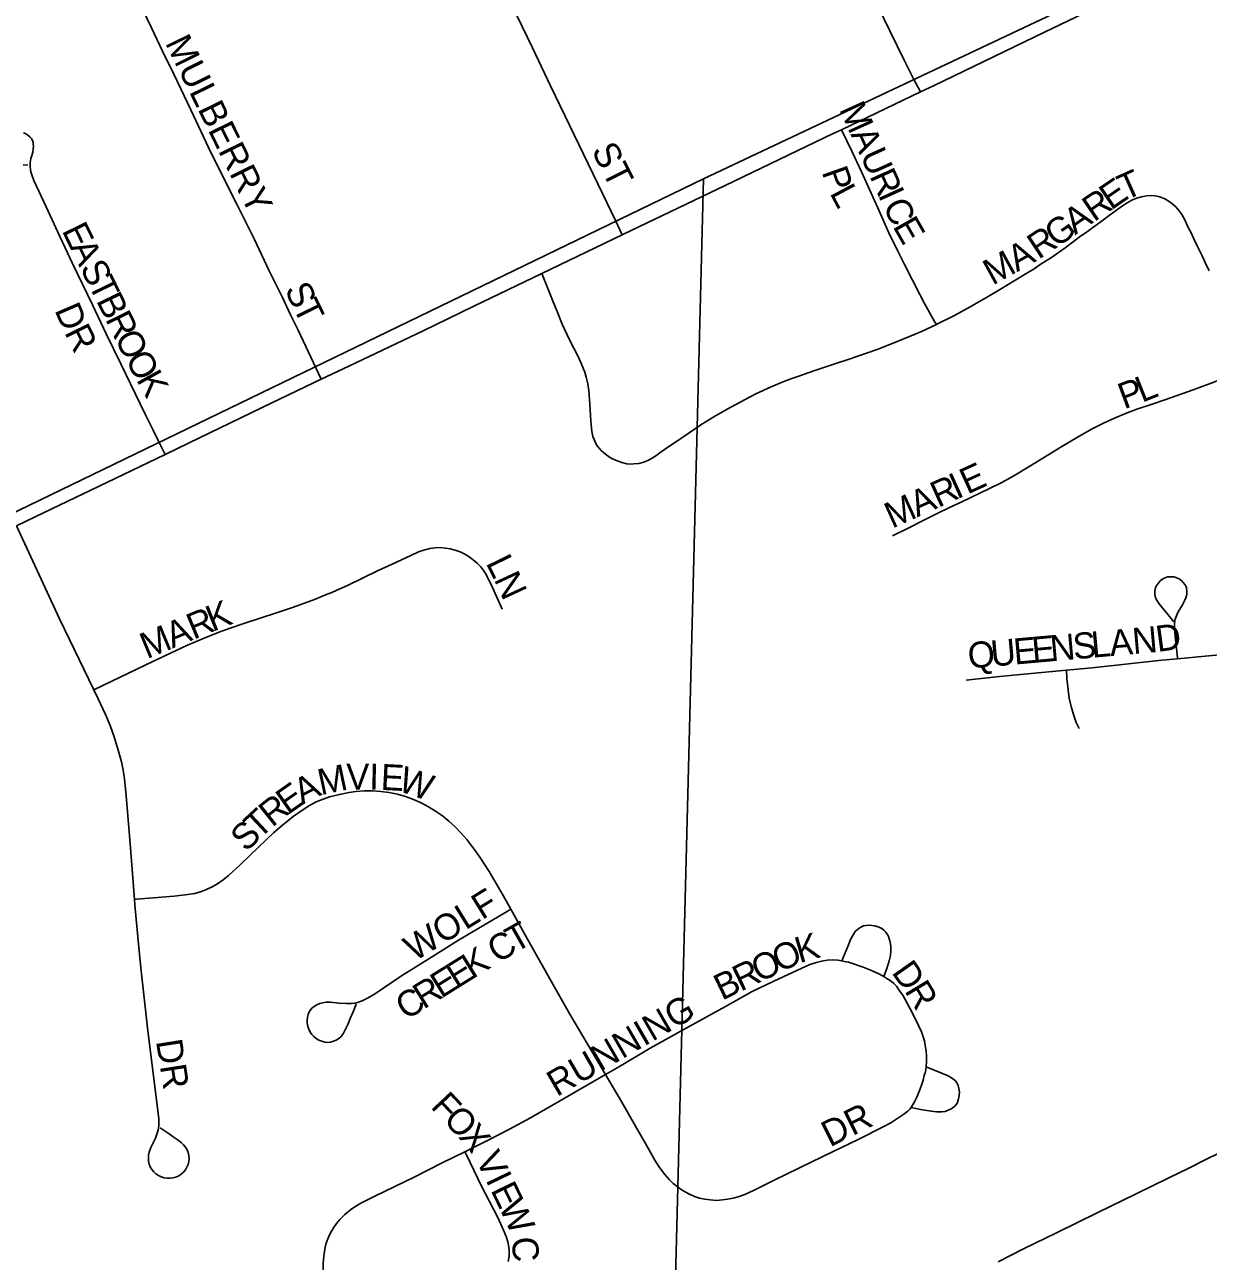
# Model space of a CAD drawing. Extents: x -5.6 to 34, y 0 to 22.
# Drawn here: x 4.822 to 5.73, y 19.139 to 20.089 of the extents above; entities that cross this region are included whole.
import ezdxf

# ---------------------------------------------------------------- set-up
doc = ezdxf.new("R2010")
doc.units = 0
for name, color, linetype in [('GM_X_City_Street', 7, 'Continuous'), ('GM_X_City_Street_Text', 7, 'Continuous'), ('GM_X_Section', 7, 'Continuous')]:
    doc.layers.add(name, color=color, linetype=linetype)

msp = doc.modelspace()

# ---------------------------------------------------------------- linework, layer by layer
at = {"layer": 'GM_X_City_Street'}
for points in [[(5.50953, 20.03721), (5.5046, 20.0469), (5.49712, 20.0616), (5.48598, 20.08416), (5.47718, 20.10263), (5.46985, 20.11815), (5.46339, 20.13133), (5.4585, 20.14256), (5.4546, 20.15067), (5.45137, 20.1574), (5.44667, 20.16679), (5.44052, 20.17967), (5.43679, 20.18727), (5.42703, 20.20751), (5.41793, 20.22684), (5.39456, 20.2753), (5.39379, 20.27694)], [(5.28072, 19.92757), (5.27549, 19.93857), (5.26565, 19.95932), (5.22564, 20.042), (5.21184, 20.071), (5.2001, 20.0953), (5.18545, 20.12579), (5.17342, 20.15127), (5.16593, 20.16686)], [(5.50953, 20.03721), (5.5196, 20.04202), (5.60472, 20.08318), (5.67096, 20.11508), (5.69762, 20.12785)], [(5.04967, 19.81662), (5.04581, 19.82478), (5.0316, 19.85482), (5.02615, 19.86609), (5.01999, 19.87927), (5.00943, 19.90037), (4.99841, 19.92381), (4.9848, 19.95105), (4.96515, 19.9903), (4.9496, 20.02341), (4.9367, 20.05037), (4.92789, 20.06853), (4.91931, 20.08641), (4.90619, 20.11424)], [(5.44896, 20.00822), (5.50953, 20.03721)], [(5.28072, 19.92757), (5.28158, 19.92799), (5.3597, 19.9655), (5.44262, 20.00519), (5.44896, 20.00822)], [(5.52176, 19.8586), (5.52043, 19.86099), (5.51259, 19.87488), (5.50911, 19.88166), (5.50351, 19.89268), (5.49729, 19.90467), (5.49208, 19.915), (5.4854, 19.92911), (5.4768, 19.94836), (5.46443, 19.97593), (5.45716, 19.99112), (5.44896, 20.00822)], [(4.92978, 19.75883), (4.9243, 19.77016), (4.92044, 19.77813), (4.91459, 19.78983), (4.90338, 19.81297), (4.89574, 19.82849), (4.88467, 19.85151), (4.87415, 19.87386), (4.85852, 19.90606), (4.84757, 19.92957), (4.83854, 19.9489), (4.82894, 19.96927), (4.82742, 19.97345), (4.82656, 19.97681), (4.82623, 19.98036), (4.82624, 19.98293), (4.82687, 19.98612), (4.82755, 19.98843), (4.82822, 19.99108), (4.82866, 19.99351), (4.82873, 19.99541), (4.82866, 19.99727), (4.82843, 19.9987), (4.82778, 20.00037), (4.82721, 20.00137), (4.82601, 20.0028), (4.82446, 20.00412), (4.82301, 20.00512), (4.82114, 20.00578)], [(4.82093, 19.98091), (4.82447, 19.98124)], [(5.73117, 19.89987), (5.72813, 19.90625), (5.72569, 19.91129), (5.72197, 19.91898), (5.71943, 19.92431), (5.717, 19.92952), (5.71491, 19.93369), (5.71352, 19.93664), (5.71213, 19.93942), (5.71022, 19.94307), (5.70808, 19.94595), (5.70554, 19.94897), (5.70365, 19.95076), (5.70049, 19.95311), (5.69707, 19.95505), (5.69465, 19.95609), (5.69216, 19.9569), (5.68959, 19.95739), (5.68699, 19.9576), (5.68305, 19.95743), (5.67918, 19.95672), (5.67541, 19.95557), (5.6718, 19.954), (5.66835, 19.95211), (5.66397, 19.94923), (5.65999, 19.94637), (5.65545, 19.9431), (5.65028, 19.9394), (5.64159, 19.93297), (5.63691, 19.92966), (5.63149, 19.92559), (5.62579, 19.92131), (5.62075, 19.9175), (5.61641, 19.91436), (5.6093, 19.90949), (5.60234, 19.90515), (5.59679, 19.9015), (5.59123, 19.89802), (5.58287, 19.89289), (5.57108, 19.88567), (5.56031, 19.87941), (5.54553, 19.87088), (5.53515, 19.86525), (5.52224, 19.85882), (5.52176, 19.8586)], [(5.21888, 19.89774), (5.28072, 19.92757)], [(5.1467, 19.86297), (5.16686, 19.87265), (5.21888, 19.89774)], [(5.52176, 19.8586), (5.5103, 19.85339), (5.50548, 19.85131), (5.4873, 19.84377), (5.47625, 19.83958), (5.45396, 19.83181), (5.44527, 19.82886), (5.42785, 19.82311), (5.41553, 19.81882), (5.41072, 19.81719), (5.40469, 19.81495), (5.3951, 19.81082), (5.38322, 19.80532), (5.37506, 19.80112), (5.36128, 19.79352), (5.35098, 19.78772), (5.34091, 19.78154), (5.32783, 19.77276), (5.31377, 19.76309), (5.31061, 19.76079), (5.30753, 19.75849), (5.30426, 19.75633), (5.30081, 19.75449), (5.29717, 19.75306), (5.29338, 19.75204), (5.28948, 19.75154), (5.28686, 19.75151), (5.28425, 19.75176), (5.28041, 19.75256), (5.27671, 19.75387), (5.27314, 19.75553), (5.27089, 19.75687), (5.26774, 19.75921), (5.26485, 19.76167), (5.26304, 19.76358), (5.26144, 19.76559), (5.26011, 19.76788), (5.25905, 19.77028), (5.25821, 19.77277), (5.25736, 19.7766), (5.25671, 19.78183), (5.25652, 19.78444), (5.25581, 19.7975), (5.25491, 19.80797), (5.25418, 19.81315), (5.25304, 19.81828), (5.2519, 19.82204), (5.2495, 19.82813), (5.24678, 19.8341), (5.24023, 19.84697), (5.23469, 19.85887), (5.23064, 19.86856), (5.22707, 19.87742), (5.22346, 19.88639), (5.21888, 19.89774)], [(5.04967, 19.81662), (5.07091, 19.82676), (5.1278, 19.85389), (5.1467, 19.86297)], [(5.48813, 19.69629), (5.50077, 19.70248), (5.51314, 19.70883), (5.5225, 19.71348), (5.53194, 19.71802), (5.54141, 19.72255), (5.56267, 19.73268), (5.57201, 19.73743), (5.5812, 19.74248), (5.59358, 19.7499), (5.60808, 19.75886), (5.61816, 19.76502), (5.63054, 19.7724), (5.64082, 19.7782), (5.65016, 19.78297), (5.6585, 19.78679), (5.66694, 19.79037), (5.67553, 19.79357), (5.68673, 19.79715), (5.69789, 19.80095), (5.71893, 19.80836), (5.73486, 19.81441), (5.75184, 19.82152), (5.76526, 19.82774)], [(4.92978, 19.75883), (4.94787, 19.76754), (5.01167, 19.79847), (5.04967, 19.81662)], [(4.81572, 19.7041), (4.83069, 19.71128), (4.88515, 19.73739), (4.92978, 19.75883)], [(4.87507, 19.57818), (4.84867, 19.6326), (4.81572, 19.7041)], [(4.87507, 19.57818), (4.88904, 19.58483), (4.92099, 19.60006), (4.94705, 19.61242), (4.9615, 19.61864), (4.97246, 19.62301), (4.97985, 19.62546), (4.99027, 19.62894), (5.01599, 19.63756), (5.02846, 19.64163), (5.04444, 19.64752), (5.05415, 19.6515), (5.05661, 19.65242), (5.06974, 19.65836), (5.09334, 19.66981), (5.10413, 19.67458), (5.11831, 19.68139), (5.12432, 19.68402), (5.12927, 19.68575), (5.13309, 19.68667), (5.13699, 19.68719), (5.14091, 19.6873), (5.14484, 19.687), (5.14871, 19.68633), (5.15251, 19.68532), (5.15621, 19.68399), (5.15978, 19.68233), (5.16317, 19.68032), (5.16635, 19.67801), (5.16931, 19.67544), (5.17207, 19.67261), (5.17444, 19.6695), (5.17644, 19.66612), (5.18099, 19.65666), (5.18863, 19.63996)], [(5.70691, 19.60197), (5.70684, 19.60271), (5.70562, 19.61479), (5.70505, 19.61945), (5.70452, 19.62466), (5.70453, 19.6286), (5.70487, 19.6312), (5.70512, 19.63248), (5.70653, 19.63613), (5.70772, 19.63845), (5.71039, 19.64294), (5.71222, 19.64642), (5.71318, 19.64883), (5.71392, 19.65135), (5.71407, 19.65264), (5.7141, 19.65393), (5.71369, 19.65642), (5.71322, 19.6576), (5.71262, 19.65873), (5.71104, 19.66082), (5.71014, 19.66175), (5.70911, 19.66257), (5.70802, 19.6633), (5.70565, 19.66441), (5.7044, 19.66478), (5.70312, 19.66498), (5.70052, 19.66499), (5.69926, 19.66477), (5.69801, 19.6644), (5.69565, 19.66327), (5.69356, 19.66173), (5.69266, 19.66083), (5.69116, 19.65883), (5.69057, 19.65772), (5.69007, 19.65652), (5.68972, 19.65528), (5.68948, 19.65399), (5.68938, 19.65267), (5.68942, 19.65135), (5.68963, 19.65005), (5.68998, 19.6488), (5.69115, 19.64646), (5.69279, 19.64407), (5.69574, 19.64036), (5.69861, 19.63709), (5.70074, 19.63453), (5.70396, 19.63045)], [(5.70691, 19.60197), (5.72819, 19.60403), (5.74974, 19.60612), (5.78238, 19.60941), (5.81759, 19.6132), (5.83812, 19.6155)], [(5.62173, 19.59327), (5.64134, 19.59511), (5.69486, 19.6008), (5.70691, 19.60197)], [(5.54464, 19.58565), (5.57027, 19.58828), (5.58905, 19.59021), (5.62173, 19.59327)], [(5.63128, 19.54836), (5.62911, 19.55309), (5.62691, 19.5592), (5.62512, 19.56545), (5.62373, 19.5718), (5.62283, 19.57823), (5.62204, 19.58671), (5.62173, 19.59327)], [(4.90623, 19.41723), (4.90443, 19.44044), (4.90211, 19.46922), (4.90003, 19.49672), (4.89854, 19.50985), (4.89753, 19.51639), (4.89623, 19.52289), (4.89389, 19.53185), (4.89074, 19.54197), (4.88755, 19.55067), (4.88401, 19.55923), (4.87846, 19.5712), (4.87507, 19.57818)], [(4.90623, 19.41723), (4.90796, 19.41738), (4.93666, 19.41969), (4.94723, 19.42088), (4.95253, 19.42185), (4.95776, 19.42328), (4.96158, 19.42469), (4.96652, 19.427), (4.97005, 19.42906), (4.97448, 19.43218), (4.9786, 19.43563), (4.98732, 19.44372), (5.00156, 19.45743), (5.01305, 19.46828), (5.01993, 19.47431), (5.02804, 19.48083), (5.03543, 19.48601), (5.04068, 19.48943), (5.04577, 19.49223), (5.05124, 19.49429), (5.05607, 19.49591), (5.06359, 19.49788), (5.07116, 19.49941), (5.07624, 19.50009), (5.08264, 19.50049), (5.08908, 19.50044), (5.09551, 19.5), (5.10187, 19.49918), (5.10816, 19.49789), (5.11432, 19.49614), (5.12036, 19.49395), (5.12623, 19.49135), (5.13192, 19.48835), (5.13741, 19.48499), (5.14268, 19.4813), (5.1477, 19.47729), (5.15241, 19.47294), (5.15679, 19.46824), (5.16144, 19.46318), (5.16457, 19.45923), (5.16782, 19.45477), (5.17136, 19.44973), (5.17513, 19.44382), (5.1785, 19.43853), (5.18929, 19.42032), (5.19524, 19.40962)], [(4.92612, 19.24176), (4.92984, 19.23915), (4.93295, 19.23716), (4.93602, 19.23494), (4.93908, 19.23273), (4.94224, 19.23041), (4.94397, 19.22884), (4.94544, 19.22702), (4.94662, 19.22503), (4.94749, 19.22288), (4.94801, 19.22062), (4.94817, 19.21831), (4.94799, 19.216), (4.94747, 19.21373), (4.9466, 19.21158), (4.94543, 19.20958), (4.94397, 19.20779), (4.94224, 19.20624), (4.9403, 19.20496), (4.93817, 19.20399), (4.93593, 19.20334), (4.93362, 19.20302), (4.93131, 19.20302), (4.929, 19.20339), (4.92679, 19.2041), (4.92469, 19.20513), (4.92278, 19.20646), (4.92106, 19.20805), (4.91959, 19.20986), (4.91842, 19.21185), (4.91758, 19.21402), (4.91709, 19.21625), (4.91695, 19.21855), (4.91712, 19.22084), (4.91765, 19.22317), (4.91898, 19.22663), (4.92238, 19.2338), (4.92384, 19.23764), (4.92454, 19.24038), (4.92498, 19.24319), (4.92509, 19.24597), (4.92492, 19.24876), (4.92438, 19.2528), (4.91632, 19.31868), (4.91128, 19.36469), (4.90919, 19.38558), (4.90656, 19.41298), (4.90623, 19.41723)], [(5.07636, 19.33666), (5.07422, 19.33092), (5.07196, 19.32563), (5.07007, 19.32121), (5.06806, 19.31706), (5.06662, 19.31444), (5.06482, 19.31197), (5.06306, 19.31045), (5.06106, 19.30901), (5.05898, 19.30823), (5.05679, 19.30764), (5.05459, 19.30744), (5.05232, 19.30767), (5.05005, 19.30828), (5.04787, 19.3092), (5.04582, 19.3104), (5.04397, 19.31183), (5.04236, 19.31349), (5.04103, 19.31537), (5.04002, 19.31744), (5.03931, 19.3197), (5.03893, 19.32205), (5.03883, 19.32441), (5.03904, 19.32674), (5.03956, 19.32893), (5.04043, 19.33097), (5.04106, 19.33191), (5.04251, 19.33364), (5.04431, 19.33508), (5.04631, 19.33628), (5.04848, 19.33719), (5.05078, 19.33782), (5.05313, 19.33817), (5.05681, 19.33823), (5.06324, 19.33761), (5.06864, 19.33718), (5.07282, 19.33727), (5.07558, 19.33765), (5.07833, 19.33831), (5.08097, 19.33926), (5.08471, 19.34104), (5.09045, 19.34453), (5.11121, 19.35845), (5.13423, 19.37293), (5.15498, 19.38599), (5.19186, 19.40764), (5.19524, 19.40962)], [(5.19524, 19.40962), (5.20803, 19.38674), (5.2261, 19.35435), (5.24037, 19.32918), (5.257, 19.30091), (5.26776, 19.28275)], [(5.44913, 19.36999), (5.45425, 19.38242), (5.45594, 19.3863), (5.45783, 19.38994), (5.45957, 19.39256), (5.46142, 19.39441), (5.46372, 19.39583), (5.46578, 19.39681), (5.46785, 19.39725), (5.47057, 19.39748), (5.47428, 19.39692), (5.47701, 19.39605), (5.47985, 19.39486), (5.48149, 19.39365), (5.48279, 19.39235), (5.48421, 19.39028), (5.48498, 19.38864), (5.48607, 19.38537), (5.48673, 19.38156), (5.48683, 19.37764), (5.4865, 19.37415), (5.48564, 19.37), (5.48401, 19.36499), (5.48142, 19.358)], [(5.26776, 19.28275), (5.27848, 19.28897), (5.3022, 19.30307), (5.33213, 19.31969), (5.3599, 19.33509), (5.38043, 19.34649), (5.39707, 19.35444), (5.41852, 19.36445), (5.42465, 19.36709), (5.42978, 19.36886), (5.43376, 19.36987), (5.43785, 19.37051), (5.44201, 19.37069), (5.44614, 19.37044), (5.44913, 19.36999)], [(5.44913, 19.36999), (5.45239, 19.36933), (5.45427, 19.36889), (5.45676, 19.36827), (5.46553, 19.36528), (5.47079, 19.36323), (5.47699, 19.36036), (5.48142, 19.358)], [(5.48142, 19.358), (5.48179, 19.3578), (5.48515, 19.35582), (5.48708, 19.35439), (5.48917, 19.35251), (5.49108, 19.35045), (5.49355, 19.3471), (5.49604, 19.34359), (5.49784, 19.34036), (5.50334, 19.32978)], [(5.51394, 19.28864), (5.5143, 19.29276), (5.51425, 19.29687), (5.51386, 19.30092), (5.51329, 19.30496), (5.51259, 19.30861), (5.51173, 19.31156), (5.51032, 19.3154), (5.50814, 19.32033), (5.50334, 19.32978)], [(5.50245, 19.25746), (5.50358, 19.2591), (5.50506, 19.26168), (5.50687, 19.26542), (5.50935, 19.27179), (5.51056, 19.27541), (5.51163, 19.27851), (5.51249, 19.28191), (5.51333, 19.28492), (5.51394, 19.28864)], [(5.50245, 19.25746), (5.50967, 19.25587), (5.51768, 19.25447), (5.52192, 19.25408), (5.52616, 19.25399), (5.52843, 19.25437), (5.53032, 19.25503), (5.53314, 19.25635), (5.53474, 19.25739), (5.53598, 19.25852), (5.5372, 19.25985), (5.53805, 19.26135), (5.53889, 19.26399), (5.53927, 19.26663), (5.53946, 19.26947), (5.53907, 19.2721), (5.53851, 19.27427), (5.5375, 19.2763), (5.53653, 19.27776), (5.53426, 19.27974), (5.53087, 19.28163), (5.51394, 19.28864)], [(5.15986, 19.22343), (5.17785, 19.23233), (5.19415, 19.24075), (5.21027, 19.24954), (5.23191, 19.26195), (5.26776, 19.28275)], [(5.26776, 19.28275), (5.28041, 19.26142), (5.29081, 19.24319), (5.29841, 19.22982), (5.30572, 19.21691), (5.30931, 19.2113), (5.31325, 19.20584), (5.31686, 19.20174), (5.31985, 19.19895), (5.32304, 19.19641), (5.32755, 19.19339), (5.33233, 19.19076), (5.3361, 19.18912), (5.34001, 19.18782), (5.34404, 19.18692), (5.3481, 19.18641), (5.35299, 19.18607), (5.35763, 19.18643), (5.36169, 19.18693), (5.3657, 19.18775), (5.36963, 19.18885), (5.37469, 19.19071), (5.38196, 19.19398), (5.39732, 19.20153), (5.42562, 19.21533), (5.44212, 19.22335), (5.46217, 19.23322), (5.48099, 19.24254), (5.48687, 19.24574), (5.49136, 19.24859), (5.4968, 19.25233), (5.49976, 19.25458), (5.50146, 19.25616), (5.50245, 19.25746)], [(5.05037, 19.08439), (5.05097, 19.1141), (5.05121, 19.1378), (5.0516, 19.14317), (5.05238, 19.14853), (5.0533, 19.15254), (5.05461, 19.15646), (5.05632, 19.16023), (5.05908, 19.16496), (5.06144, 19.1683), (5.06405, 19.17146), (5.06788, 19.17533), (5.07205, 19.17882), (5.0754, 19.18117), (5.08007, 19.1839), (5.0907, 19.18927), (5.12139, 19.20427), (5.14255, 19.21487), (5.15986, 19.22343)], [(5.19306, 19.13903), (5.19385, 19.14322), (5.19396, 19.14743), (5.19371, 19.15024), (5.19288, 19.15433), (5.19166, 19.15828), (5.18965, 19.16331), (5.18509, 19.17293), (5.17247, 19.19756), (5.16104, 19.221), (5.15986, 19.22343)], [(5.56932, 19.13897), (5.58855, 19.14878), (5.61409, 19.16129), (5.64581, 19.17681), (5.67511, 19.19116), (5.70027, 19.20348), (5.71564, 19.21078), (5.72714, 19.21663), (5.74011, 19.22323)]]:
    msp.add_lwpolyline(points, dxfattribs=at)
at = {"layer": 'GM_X_Section'}
for points in [[(7.5006, 20.9), (7.24978, 20.9), (7.26094, 20.87609), (5.343, 19.97061), (5.31658, 18.93519), (7.45777, 18.92939)], [(3.21828, 20.0634), (4.49244, 20.05384), (4.68808, 19.65345), (5.343, 19.97061), (5.31658, 18.93519), (3.18895, 18.98881)]]:
    msp.add_lwpolyline(points, close=True, dxfattribs=at)

# ---------------------------------------------------------------- texts
at = {"layer": 'GM_X_City_Street_Text'}
for s, rotation, p in [('MULBERRY', 296.23398, (4.92954, 20.07488)), ('M', 294.40628, (5.44692, 20.02399)), ('A', 294.40988, (5.45565, 20.00476)), ('ST', 296.56506, (5.25679, 19.99239)), ('U', 294.40416, (5.46292, 19.98873)), ('P', 289.38547, (5.43364, 19.97585)), ('R', 294.38166, (5.47019, 19.97271)), ('T', 24.14554, (5.66658, 19.95351)), ('E', 34.41505, (5.6558, 19.94602)), ('L', 298.01971, (5.43961, 19.95962)), ('I', 294.39804, (5.47673, 19.95827)), ('R', 34.39722, (5.64272, 19.93706)), ('C', 294.70622, (5.48042, 19.95016)), ('A', 34.42396, (5.6282, 19.92711)), ('E', 299.7175, (5.48791, 19.93407)), ('G', 34.40823, (5.61367, 19.91717)), ('E', 296.17405, (4.85025, 19.93076)), ('R', 33.58448, (5.60022, 19.90823)), ('A', 29.57043, (5.58361, 19.89874)), ('A', 296.16712, (4.85646, 19.91813)), ('M', 28.89538, (5.5649, 19.88841)), ('S', 296.19027, (4.86422, 19.90232)), ('T', 296.17405, (4.87044, 19.88969)), ('B', 296.17807, (4.87665, 19.87705)), ('S', 293.9736, (5.02135, 19.88582)), ('D', 293.34782, (4.84471, 19.86982)), ('T', 296.38783, (5.02746, 19.87212)), ('R', 296.1524, (4.88363, 19.86284)), ('R', 296.47871, (4.85218, 19.8526)), ('O', 296.46907, (4.89067, 19.84852)), ('O', 298.36952, (4.89884, 19.83211)), ('K', 299.04533, (4.90733, 19.81641)), ('P', 20.34496, (5.66586, 19.79338)), ('L', 21.7079, (5.67954, 19.79845)), ('E', 24.59778, (5.54561, 19.72793)), ('R', 24.38199, (5.52309, 19.71773)), ('I', 24.38178, (5.53752, 19.72427)), ('A', 24.37522, (5.50706, 19.71046)), ('M', 24.38969, (5.48782, 19.70174)), ('L', 296.38181, (5.17576, 19.67557)), ('N', 294.90336, (5.18196, 19.66307)), ('K', 21.80953, (4.96618, 19.62253)), ('R', 22.57643, (4.95162, 19.61648)), ('M', 22.56242, (4.91585, 19.60162)), ('A', 22.5442, (4.93535, 19.60973)), ('N', 5.03413, (5.67298, 19.60552)), ('D', 7.76914, (5.69155, 19.60718)), ('U', 5.03413, (5.56429, 19.59594)), ('E', 5.03365, (5.58182, 19.59748)), ('E', 5.03365, (5.59584, 19.59872)), ('N', 5.03413, (5.60987, 19.59995)), ('S', 5.05708, (5.6274, 19.6015)), ('L', 5.03365, (5.64143, 19.60274)), ('A', 5.03413, (5.65545, 19.60397)), ('Q', 5.03413, (5.54676, 19.59439)), ('M', 11.98153, (5.04928, 19.49716)), ('V', 0.30604, (5.06886, 19.50143)), ('I', 358.6444, (5.08631, 19.50152)), ('E', 357.04753, (5.09496, 19.50132)), ('W', 341.11852, (5.10758, 19.50087)), ('E', 35.00097, (5.02405, 19.48182)), ('A', 27.38602, (5.03498, 19.48954)), ('R', 38.59913, (5.01193, 19.47214)), ('T', 43.10629, (5.00197, 19.46279)), ('S', 44.49775, (4.99202, 19.45301)), ('WOLF', 31.70293, (5.12125, 19.36913)), ('T', 29.51105, (5.19837, 19.3758)), ('C', 31.02206, (5.18492, 19.3677)), ('K', 16.21561, (5.41669, 19.36807)), ('K', 31.87099, (5.16554, 19.35569)), ('O', 25.75371, (5.40166, 19.36074)), ('E', 31.9011, (5.15359, 19.34825)), ('R', 25.75047, (5.37154, 19.34621)), ('O', 25.75371, (5.38581, 19.35309)), ('D', 305.16929, (5.48699, 19.36115)), ('E', 31.93969, (5.14165, 19.3408)), ('B', 25.75047, (5.35728, 19.33933)), ('R', 31.90499, (5.12819, 19.33242)), ('R', 301.21778, (5.49693, 19.34706)), ('C', 31.90499, (5.11474, 19.32405)), ('RUNNING', 30.06888, (5.23043, 19.26534)), ('DR', 278.96909, (4.92274, 19.30841)), ('F', 313.22216, (5.13295, 19.25763)), ('O', 313.23168, (5.14259, 19.24737)), ('DR', 26.56991, (5.44007, 19.22671)), ('X', 309.62927, (5.15443, 19.23479)), ('V', 296.31093, (5.16777, 19.21778)), ('I', 295.78291, (5.17555, 19.20205)), ('E', 295.78587, (5.17938, 19.19413)), ('W', 295.09106, (5.18547, 19.18151)), ('C', 274.20501, (5.19579, 19.15748))]:
    msp.add_text(s, height=0.02, rotation=rotation, dxfattribs=at).set_placement(p)

doc.saveas('drawing.dxf')
